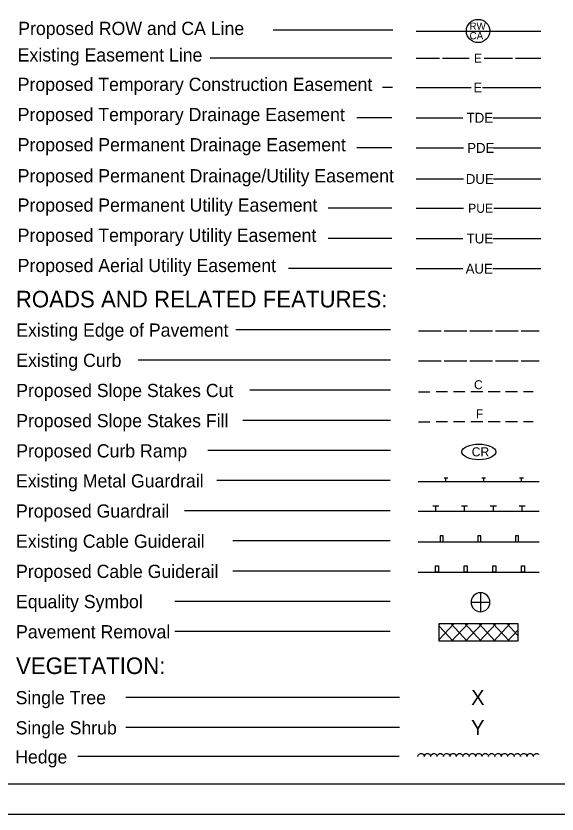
# Model space of a CAD drawing. Extents: x 2058169 to 2059852, y 675171 to 676266.
# Drawn here: x 2058730 to 2059088, y 675171 to 675700 of the extents above; entities that cross this region are included whole.
import ezdxf

# ---------------------------------------------------------------- set-up
doc = ezdxf.new("R2010")
doc.units = 0
for name, color, linetype in [('Prop Easement Permanent Drainage Utility', 7, 'Continuous'), ('Prop WCC CELL', 7, 'Continuous'), ('Sheet Block Title CELL', 7, 'Continuous'), ('Sheet Sticker Exception Certification CELL', 7, 'Continuous'), ('Sheet Symbology CELL', 7, 'Continuous')]:
    doc.layers.add(name, color=color, linetype=linetype)

msp = doc.modelspace()

# ---------------------------------------------------------------- linework, layer by layer
at = {"layer": 'Prop Easement Permanent Drainage Utility'}
for p, q in [((2058994.73, 675591.85), (2059026.03, 675591.85)), ((2059046.03, 675591.85), (2059077.23, 675591.85))]:
    msp.add_line(p, q, dxfattribs=at)
at = {"layer": 'Prop WCC CELL'}
msp.add_ellipse((2059036.23, 675411.03), major_axis=(11.21, 0), ratio=0.462467, dxfattribs=at)
at = {"layer": 'Sheet Block Title CELL'}
msp.add_lwpolyline([(2058181.54, 675191.1), (2059847.52, 675191.11), (2059847.54, 676246.1), (2058181.54, 676246.1)], close=True, dxfattribs=at)
at = {"layer": 'Sheet Sticker Exception Certification CELL'}
msp.add_lwpolyline([(2058168.54, 675171.1), (2059852.04, 675171.1), (2059852.04, 676266.1), (2058168.54, 676266.1)], close=True, dxfattribs=at)
at = {"layer": 'Sheet Symbology CELL'}
for p, q in [((2058979.33, 675690.5), (2058899.97, 675690.5)), ((2058994.74, 675689.73), (2059077.24, 675689.73)), ((2058978.7, 675671.88), (2058858.42, 675671.88)), ((2058994.73, 675671.88), (2059010.24, 675671.88)), ((2059012.24, 675671.88), (2059029.74, 675671.88)), ((2059039.74, 675671.88), (2059058.49, 675671.88)), ((2059060.49, 675671.88), (2059077.23, 675671.88)), ((2058979.08, 675652.43), (2058972.41, 675652.43)), ((2058994.73, 675652.43), (2058997.34, 675652.43)), ((2058997.34, 675652.43), (2059031.09, 675652.43)), ((2059038.59, 675652.43), (2059072.34, 675652.43)), ((2059072.34, 675652.43), (2059077.23, 675652.43)), ((2058978.7, 675632.43), (2058955.55, 675632.43)), ((2058994.73, 675632.43), (2058998.08, 675632.43)), ((2058998.08, 675632.43), (2059025.58, 675632.43)), ((2059045.58, 675632.43), (2059073.08, 675632.43)), ((2059073.08, 675632.43), (2059077.23, 675632.43)), ((2058978.7, 675612.43), (2058955.55, 675612.43)), ((2058994.73, 675612.43), (2058998.53, 675612.43)), ((2058998.53, 675612.43), (2059026.03, 675612.43)), ((2059046.03, 675612.43), (2059073.53, 675612.43)), ((2059073.53, 675612.43), (2059077.23, 675612.43)), ((2058978.7, 675572.42), (2058936.56, 675572.42)), ((2058994.73, 675572.42), (2058998.57, 675572.42)), ((2058998.57, 675572.42), (2059026.07, 675572.42)), ((2059046.07, 675572.42), (2059073.57, 675572.42)), ((2059073.57, 675572.42), (2059077.23, 675572.42)), ((2058978.7, 675552.42), (2058936.56, 675552.42)), ((2058994.73, 675552.42), (2058998.08, 675552.42)), ((2058998.08, 675552.42), (2059025.58, 675552.42)), ((2059045.58, 675552.42), (2059073.08, 675552.42)), ((2059073.08, 675552.42), (2059077.23, 675552.42)), ((2058978.7, 675532.42), (2058910.24, 675532.42)), ((2058994.73, 675532.42), (2058998.08, 675532.42)), ((2058998.08, 675532.42), (2059025.58, 675532.42)), ((2059045.58, 675532.42), (2059073.08, 675532.42)), ((2059073.08, 675532.42), (2059077.23, 675532.42)), ((2058977.74, 675491.89), (2058875.39, 675491.89)), ((2058996.27, 675491.32), (2059011.27, 675491.32)), ((2059013.27, 675491.32), (2059028.27, 675491.32)), ((2059030.27, 675491.32), (2059045.27, 675491.32)), ((2059047.27, 675491.32), (2059062.27, 675491.32)), ((2059064.27, 675491.32), (2059076.27, 675491.32)), ((2058977.74, 675471.89), (2058810.59, 675471.89)), ((2058996.27, 675471.32), (2059011.27, 675471.32)), ((2059013.27, 675471.32), (2059028.27, 675471.32)), ((2059030.27, 675471.32), (2059045.27, 675471.32)), ((2059047.27, 675471.32), (2059062.27, 675471.32)), ((2059064.27, 675471.32), (2059076.27, 675471.32)), ((2058977.74, 675451.89), (2058884.55, 675451.89)), ((2058996.27, 675450.84), (2059003.87, 675450.84)), ((2059015.57, 675450.84), (2059008.02, 675450.84)), ((2059027.07, 675450.84), (2059019.47, 675450.84)), ((2059038.82, 675450.84), (2059031.02, 675450.84)), ((2059050.27, 675450.84), (2059042.52, 675450.84)), ((2059061.82, 675450.84), (2059053.97, 675450.84)), ((2059072.12, 675450.84), (2059065.72, 675450.84)), ((2058977.74, 675431.89), (2058880, 675431.89)), ((2058996.27, 675430.84), (2059003.87, 675430.84)), ((2059015.57, 675430.84), (2059008.02, 675430.84)), ((2059027.07, 675430.84), (2059019.47, 675430.84)), ((2059038.82, 675430.84), (2059031.02, 675430.84)), ((2059050.27, 675430.84), (2059042.52, 675430.84)), ((2059061.82, 675430.84), (2059053.97, 675430.84)), ((2059072.12, 675430.84), (2059065.72, 675430.84)), ((2058977.74, 675411.89), (2058856.81, 675411.89)), ((2058977.58, 675392.01), (2058862.74, 675392.01)), ((2058996.11, 675391.44), (2059076.11, 675391.44)), ((2059013.25, 675393.94), (2059015.75, 675393.94)), ((2059014.5, 675391.44), (2059014.5, 675393.94)), ((2059038.25, 675393.94), (2059040.75, 675393.94)), ((2059039.5, 675391.44), (2059039.5, 675393.94)), ((2059063.25, 675393.94), (2059065.75, 675393.94)), ((2059064.5, 675391.44), (2059064.5, 675393.94)), ((2059005.84, 675375.39), (2059009.84, 675375.39)), ((2059007.84, 675371.44), (2059007.84, 675375.39)), ((2059024.84, 675375.39), (2059028.84, 675375.39)), ((2059026.84, 675371.44), (2059026.84, 675375.39)), ((2059043.84, 675375.39), (2059047.84, 675375.39)), ((2059045.84, 675371.44), (2059045.84, 675375.39)), ((2059062.84, 675375.39), (2059066.84, 675375.39)), ((2059064.84, 675371.44), (2059064.84, 675375.39)), ((2058977.58, 675372.01), (2058841.34, 675372.01)), ((2059076.11, 675371.44), (2058996.11, 675371.44)), ((2058977.58, 675352.01), (2058873.28, 675352.01)), ((2058996.11, 675351.44), (2059076.11, 675351.44)), ((2058977.58, 675332.01), (2058873.28, 675332.01)), ((2058996.11, 675331.44), (2059076.11, 675331.44)), ((2059037.34, 675317.68), (2059037.34, 675311.43)), ((2058977.58, 675312.01), (2058834.96, 675312.01)), ((2059031.09, 675311.43), (2059037.34, 675311.43)), ((2059037.34, 675311.43), (2059037.34, 675305.18)), ((2059037.34, 675311.43), (2059043.59, 675311.43)), ((2059010.06, 675297.3), (2059062.16, 675297.3)), ((2059010.06, 675285.6), (2059010.06, 675297.3)), ((2059010.06, 675296.7), (2059010.61, 675297.3)), ((2059010.06, 675286.75), (2059019.91, 675297.3)), ((2059019.31, 675285.6), (2059010.06, 675295.5)), ((2059028.61, 675285.6), (2059017.61, 675297.3)), ((2059018.21, 675285.6), (2059029.21, 675297.3)), ((2059037.86, 675285.6), (2059026.91, 675297.3)), ((2059027.46, 675285.6), (2059038.51, 675297.3)), ((2059047.16, 675285.6), (2059036.16, 675297.3)), ((2059036.76, 675285.6), (2059047.76, 675297.3)), ((2059056.46, 675285.6), (2059045.41, 675297.3)), ((2059046.06, 675285.6), (2059057.01, 675297.3)), ((2059062.16, 675289.35), (2059054.71, 675297.3)), ((2059062.16, 675297.3), (2059062.16, 675285.6)), ((2058977.58, 675292.01), (2058834.96, 675292.01)), ((2059055.31, 675285.6), (2059062.16, 675292.9)), ((2059062.16, 675285.6), (2059010.06, 675285.6)), ((2058983.72, 675248.37), (2058802.59, 675248.37)), ((2058983.72, 675228.37), (2058802.59, 675228.37)), ((2058996.14, 675210.06), (2058996.74, 675210.71)), ((2058996.74, 675210.71), (2058997.54, 675211.16)), ((2058997.54, 675211.16), (2058998.49, 675211.16)), ((2058998.49, 675211.16), (2058999.29, 675210.66)), ((2058999.29, 675210.66), (2058999.84, 675210.01)), ((2059000.39, 675210.06), (2059000.99, 675210.71)), ((2059000.99, 675210.71), (2059001.79, 675211.16)), ((2059001.79, 675211.16), (2059002.74, 675211.16)), ((2059002.74, 675211.16), (2059003.54, 675210.66)), ((2059003.54, 675210.66), (2059004.09, 675210.01)), ((2059004.64, 675210.06), (2059005.24, 675210.71)), ((2059005.24, 675210.71), (2059006.04, 675211.16)), ((2059006.04, 675211.16), (2059006.99, 675211.16)), ((2059006.99, 675211.16), (2059007.79, 675210.66)), ((2059007.79, 675210.66), (2059008.34, 675210.01)), ((2059008.89, 675210.06), (2059009.49, 675210.71)), ((2059009.49, 675210.71), (2059010.29, 675211.16)), ((2059010.29, 675211.16), (2059011.24, 675211.16)), ((2059011.24, 675211.16), (2059012.04, 675210.66)), ((2059012.04, 675210.66), (2059012.59, 675210.01)), ((2059013.14, 675210.06), (2059013.74, 675210.71)), ((2059013.74, 675210.71), (2059014.54, 675211.16)), ((2059014.54, 675211.16), (2059015.49, 675211.16)), ((2059015.49, 675211.16), (2059016.29, 675210.66)), ((2059016.29, 675210.66), (2059016.84, 675210.01)), ((2059017.39, 675210.06), (2059017.99, 675210.71)), ((2059017.99, 675210.71), (2059018.79, 675211.16)), ((2059018.79, 675211.16), (2059019.74, 675211.16)), ((2059019.74, 675211.16), (2059020.54, 675210.66)), ((2059020.54, 675210.66), (2059021.09, 675210.01)), ((2059021.64, 675210.06), (2059022.24, 675210.71)), ((2059022.24, 675210.71), (2059023.04, 675211.16)), ((2059023.04, 675211.16), (2059023.99, 675211.16)), ((2059023.99, 675211.16), (2059024.79, 675210.66)), ((2059024.79, 675210.66), (2059025.34, 675210.01)), ((2059025.89, 675210.06), (2059026.49, 675210.71)), ((2059026.49, 675210.71), (2059027.29, 675211.16)), ((2059027.29, 675211.16), (2059028.24, 675211.16)), ((2059028.24, 675211.16), (2059029.04, 675210.66)), ((2059029.04, 675210.66), (2059029.59, 675210.01)), ((2059030.14, 675210.06), (2059030.74, 675210.71)), ((2059030.74, 675210.71), (2059031.54, 675211.16)), ((2059031.54, 675211.16), (2059032.49, 675211.16)), ((2059032.49, 675211.16), (2059033.29, 675210.66)), ((2059033.29, 675210.66), (2059033.84, 675210.01)), ((2059034.39, 675210.06), (2059034.99, 675210.71)), ((2059034.99, 675210.71), (2059035.79, 675211.16)), ((2059035.79, 675211.16), (2059036.74, 675211.16)), ((2059036.74, 675211.16), (2059037.54, 675210.66)), ((2059037.54, 675210.66), (2059038.09, 675210.01)), ((2059038.64, 675210.06), (2059039.24, 675210.71)), ((2059039.24, 675210.71), (2059040.04, 675211.16)), ((2059040.04, 675211.16), (2059040.99, 675211.16)), ((2059040.99, 675211.16), (2059041.79, 675210.66)), ((2059041.79, 675210.66), (2059042.34, 675210.01)), ((2059042.89, 675210.06), (2059043.49, 675210.71)), ((2059043.49, 675210.71), (2059044.29, 675211.16)), ((2059044.29, 675211.16), (2059045.24, 675211.16)), ((2059045.24, 675211.16), (2059046.04, 675210.66)), ((2059046.04, 675210.66), (2059046.59, 675210.01)), ((2059047.14, 675210.06), (2059047.74, 675210.71)), ((2059047.74, 675210.71), (2059048.54, 675211.16)), ((2059048.54, 675211.16), (2059049.49, 675211.16)), ((2059049.49, 675211.16), (2059050.29, 675210.66)), ((2059050.29, 675210.66), (2059050.84, 675210.01)), ((2059051.39, 675210.06), (2059051.99, 675210.71)), ((2059051.99, 675210.71), (2059052.79, 675211.16)), ((2059052.79, 675211.16), (2059053.74, 675211.16)), ((2059053.74, 675211.16), (2059054.54, 675210.66)), ((2059054.54, 675210.66), (2059055.09, 675210.01)), ((2059055.64, 675210.06), (2059056.24, 675210.71)), ((2059056.24, 675210.71), (2059057.04, 675211.16)), ((2059057.04, 675211.16), (2059057.99, 675211.16)), ((2059057.99, 675211.16), (2059058.79, 675210.66)), ((2059058.79, 675210.66), (2059059.34, 675210.01)), ((2059059.89, 675210.06), (2059060.49, 675210.71)), ((2059060.49, 675210.71), (2059061.29, 675211.16)), ((2059061.29, 675211.16), (2059062.24, 675211.16)), ((2059062.24, 675211.16), (2059063.04, 675210.66)), ((2059063.04, 675210.66), (2059063.59, 675210.01)), ((2059064.14, 675210.06), (2059064.74, 675210.71)), ((2059064.74, 675210.71), (2059065.54, 675211.16)), ((2059065.54, 675211.16), (2059066.49, 675211.16)), ((2059066.49, 675211.16), (2059067.29, 675210.66)), ((2059067.29, 675210.66), (2059067.84, 675210.01)), ((2059068.39, 675210.06), (2059068.99, 675210.71)), ((2059068.99, 675210.71), (2059069.79, 675211.16)), ((2059069.79, 675211.16), (2059070.74, 675211.16)), ((2059070.74, 675211.16), (2059071.54, 675210.66)), ((2059071.54, 675210.66), (2059072.09, 675210.01)), ((2059072.64, 675210.06), (2059073.24, 675210.71)), ((2059073.24, 675210.71), (2059074.04, 675211.16)), ((2059074.04, 675211.16), (2059074.99, 675211.16)), ((2059074.99, 675211.16), (2059075.79, 675210.66)), ((2059075.79, 675210.66), (2059075.84, 675210.61)), ((2058983.45, 675209.11), (2058770.76, 675209.11)), ((2058995.84, 675209.11), (2058996.14, 675210.06)), ((2058999.84, 675210.01), (2059000.04, 675209.16)), ((2059000.09, 675209.11), (2059000.39, 675210.06)), ((2059004.09, 675210.01), (2059004.29, 675209.16)), ((2059004.34, 675209.11), (2059004.64, 675210.06)), ((2059008.34, 675210.01), (2059008.54, 675209.16)), ((2059008.59, 675209.11), (2059008.89, 675210.06)), ((2059012.59, 675210.01), (2059012.79, 675209.16)), ((2059012.84, 675209.11), (2059013.14, 675210.06)), ((2059016.84, 675210.01), (2059017.04, 675209.16)), ((2059017.09, 675209.11), (2059017.39, 675210.06)), ((2059021.09, 675210.01), (2059021.29, 675209.16)), ((2059021.34, 675209.11), (2059021.64, 675210.06)), ((2059025.34, 675210.01), (2059025.54, 675209.16)), ((2059025.59, 675209.11), (2059025.89, 675210.06)), ((2059029.59, 675210.01), (2059029.79, 675209.16)), ((2059029.84, 675209.11), (2059030.14, 675210.06)), ((2059033.84, 675210.01), (2059034.04, 675209.16)), ((2059034.09, 675209.11), (2059034.39, 675210.06)), ((2059038.09, 675210.01), (2059038.29, 675209.16)), ((2059038.34, 675209.11), (2059038.64, 675210.06)), ((2059042.34, 675210.01), (2059042.54, 675209.16)), ((2059042.59, 675209.11), (2059042.89, 675210.06)), ((2059046.59, 675210.01), (2059046.79, 675209.16)), ((2059046.84, 675209.11), (2059047.14, 675210.06)), ((2059050.84, 675210.01), (2059051.04, 675209.16)), ((2059051.09, 675209.11), (2059051.39, 675210.06)), ((2059055.09, 675210.01), (2059055.29, 675209.16)), ((2059055.34, 675209.11), (2059055.64, 675210.06)), ((2059059.34, 675210.01), (2059059.54, 675209.16)), ((2059059.59, 675209.11), (2059059.89, 675210.06)), ((2059063.59, 675210.01), (2059063.79, 675209.16)), ((2059063.84, 675209.11), (2059064.14, 675210.06)), ((2059067.84, 675210.01), (2059068.04, 675209.16)), ((2059068.09, 675209.11), (2059068.39, 675210.06)), ((2059072.09, 675210.01), (2059072.29, 675209.16)), ((2059072.34, 675209.11), (2059072.64, 675210.06))]:
    msp.add_line(p, q, dxfattribs=at)
for points in [[(2059010.59, 675351.44), (2059012.59, 675351.44), (2059012.59, 675355.44), (2059010.59, 675355.44)], [(2059035.59, 675351.44), (2059037.59, 675351.44), (2059037.59, 675355.44), (2059035.59, 675355.44)], [(2059060.59, 675351.44), (2059062.59, 675351.44), (2059062.59, 675355.44), (2059060.59, 675355.44)], [(2059007.57, 675335.44), (2059009.57, 675335.44), (2059009.57, 675331.44), (2059007.57, 675331.44)], [(2059026.57, 675335.44), (2059028.57, 675335.44), (2059028.57, 675331.44), (2059026.57, 675331.44)], [(2059045.57, 675335.44), (2059047.57, 675335.44), (2059047.57, 675331.44), (2059045.57, 675331.44)], [(2059064.57, 675335.44), (2059066.57, 675335.44), (2059066.57, 675331.44), (2059064.57, 675331.44)]]:
    msp.add_lwpolyline(points, close=True, dxfattribs=at)
msp.add_circle((2059035.73, 675689.88), 7.72, dxfattribs=at)
for start, end in [(89.9944, 179.9989), (359.9944, 89.9989), (179.9944, 269.9989), (269.9944, 359.9989)]:
    msp.add_arc((2059037.34, 675311.42), 6.25, start, end, dxfattribs=at)

# ---------------------------------------------------------------- texts
at = {"layer": 'Prop Easement Permanent Drainage Utility'}
msp.add_text('DUE', height=6.55, rotation=360, dxfattribs=at).set_placement((2059027.62, 675588.55))
at = {"layer": 'Prop WCC CELL'}
msp.add_text('CR', height=6, rotation=360, dxfattribs=at).set_placement((2059031.52, 675408.07))
at = {"layer": 'Sheet Symbology CELL'}
for s, height, p in [('Proposed ROW and CA Line', 8.75, (2058731.31, 675687.22)), ('RW', 4.838, (2059030.06, 675690.65)), ('CA', 4.838, (2059030.12, 675684.36)), ('Existing Easement Line', 8.75, (2058730.95, 675669.62)), ('E', 6, (2059032.94, 675668.88)), ('Proposed Temporary Construction Easement', 8.75, (2058730.95, 675650.17)), ('E', 6.55, (2059032.69, 675649.13)), ('Proposed Temporary Drainage Easement', 8.75, (2058730.95, 675630.17)), ('TDE', 6.55, (2059028.18, 675629.13)), ('Proposed Permanent Drainage Easement', 8.75, (2058730.95, 675610.17)), ('PDE', 6.55, (2059028.53, 675609.13)), ('Proposed Permanent Drainage/Utility Easement', 8.75, (2058730.95, 675589.59)), ('Proposed Permanent Utility Easement', 8.75, (2058730.95, 675570.16)), ('PUE', 6, (2059029.17, 675569.42)), ('Proposed Temporary Utility Easement', 8.75, (2058730.95, 675550.16)), ('TUE', 6.55, (2059028.16, 675549.12)), ('Proposed Aerial Utility Easement', 8.75, (2058730.95, 675530.16)), ('AUE', 6.55, (2059027.51, 675529.12)), ('ROADS AND RELATED FEATURES:', 11, (2058729.69, 675506.74)), ('Existing Edge of Pavement', 8.75, (2058729.99, 675487.34)), ('Existing Curb', 8.75, (2058729.99, 675467.34)), ('Proposed Slope Stakes Cut', 8.75, (2058729.99, 675447.34)), ('C', 5.93, (2059033.07, 675452.58)), ('F', 5.93, (2059034.27, 675433.21)), ('Proposed Slope Stakes Fill', 8.75, (2058729.99, 675427.34)), ('Proposed Curb Ramp', 8.75, (2058729.99, 675407.34)), ('Existing Metal Guardrail', 8.75, (2058729.83, 675387.46)), ('Proposed Guardrail', 8.75, (2058729.84, 675367.48)), ('Existing Cable Guiderail', 8.75, (2058729.84, 675347.48)), ('Proposed Cable Guiderail', 8.75, (2058729.84, 675327.48)), ('Equality Symbol', 8.75, (2058729.84, 675307.48)), ('Pavement Removal', 8.75, (2058729.84, 675287.48)), ('VEGETATION:', 11, (2058729.83, 675263.82)), ('Single Tree', 8.75, (2058729.56, 675243.84)), ('X', 10, (2059031.11, 675243.37)), ('Single Shrub', 8.75, (2058729.56, 675223.84)), ('Y', 10, (2059031.11, 675223.37)), ('Hedge', 8.75, (2058729.29, 675204.59))]:
    msp.add_text(s, height=height, rotation=360, dxfattribs=at).set_placement(p)

doc.saveas('drawing.dxf')
